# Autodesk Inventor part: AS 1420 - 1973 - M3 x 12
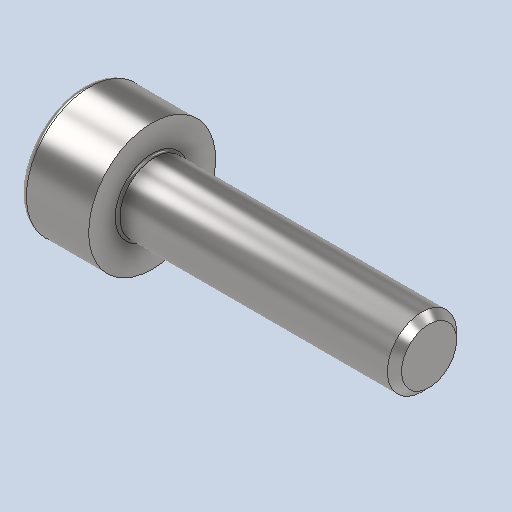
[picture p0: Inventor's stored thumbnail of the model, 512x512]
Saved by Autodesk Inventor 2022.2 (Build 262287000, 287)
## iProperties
Created: 2024-01
Part Number: AS 1420 - 1973 - M3 x 12
Material: Acciaio, Dolce
Document SubType Name: Modeling
Designer: 18907419
Density: 7.85 g/cm^3
Appearance: Default
Author: 18907419
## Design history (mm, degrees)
feature "Solid1"
node "Solido1"
